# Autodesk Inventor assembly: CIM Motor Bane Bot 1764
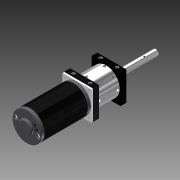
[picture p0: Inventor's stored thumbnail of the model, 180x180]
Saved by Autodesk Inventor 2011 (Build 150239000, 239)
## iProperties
Created: 2008-01
Part Number: CIM Motor Bane Bot 1764
Document SubType Name: Assembly
Designer: clee1
Author: clee1
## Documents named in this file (8)
- R:\CAD Archives\Motors\CIM Motor Bane Bots 1764\CIM Motor Bane Bot 1764.iam
- R:\CAD Archives\Motors\CIM Motor Bane Bots 1764\BB2-InterfacePlate 1764.ipt
- R:\CAD Archives\Motors\CIM Motor Bane Bots 1764\BB2-BackPlate 1764.ipt
- R:\CAD Archives\Motors\CIM Motor Bane Bots 1764\BB2-FrontPlate 1764.ipt
- R:\CAD Archives\Motors\CIM Motor Bane Bots 1764\CIM Bearing 1764.ipt
- R:\CAD Archives\Motors\CIM Motor Bane Bots 1764\BB2-RingGear 1764.ipt
- R:\CAD Archives\Motors\CIM Motor Bane Bots 1764\BB2-OutputShaft 2008 Cut 1764.ipt
- R:\CAD Archives\Motors\CIM Motor Bane Bots 1764\CIM Motor 1764.ipt
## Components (8 placed, 7 different names)
1. BB2-InterfacePlate 1764:1 — Mate:1, Flush:1, Flush:2, Mate:12
2. BB2-BackPlate 1764:1 — Mate:1, Flush:1, Flush:2, Mate:5, Mate:6, Angle:1, Angle:2, Mate:11, Angle:4, Flush:3, Flush:4
3. BB2-FrontPlate 1764:1 — Angle:2, Tangent:1, Tangent:2, Mate:13, Flush:3, Flush:4, Flush:5
4. CIM Bearing 1764:3 — Mate:3, Tangent:2
5. CIM Bearing 1764:4 — Mate:3, Tangent:1, Tangent:3, Flush:5, Mate:14
6. BB2-RingGear 1764:1 — Mate:5, Mate:6, Angle:1, Mate:13
7. BB2-OutputShaft 2008 Cut 1764:1 — Tangent:3, Mate:14, Mate:15
8. CIM Motor 1764:1 — Mate:11, Angle:4, Mate:12, Mate:15
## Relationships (20: Mate 9, Flush 5, Angle 3, Tangent 3)
- Mate:1: BB2-InterfacePlate 1764:1 ↔ BB2-BackPlate 1764:1
- Flush:1: BB2-InterfacePlate 1764:1 ↔ BB2-BackPlate 1764:1
- Flush:2: BB2-InterfacePlate 1764:1 ↔ BB2-BackPlate 1764:1
- Mate:3: CIM Bearing 1764:3 ↔ CIM Bearing 1764:4
- Mate:5: BB2-BackPlate 1764:1 ↔ BB2-RingGear 1764:1
- Mate:6: BB2-BackPlate 1764:1 ↔ BB2-RingGear 1764:1
- Angle:1: BB2-BackPlate 1764:1 ↔ BB2-RingGear 1764:1
- Angle:2: BB2-BackPlate 1764:1 ↔ BB2-FrontPlate 1764:1
- Mate:11: BB2-BackPlate 1764:1 ↔ CIM Motor 1764:1
- Angle:4: BB2-BackPlate 1764:1 ↔ CIM Motor 1764:1
- Mate:12: BB2-InterfacePlate 1764:1 ↔ CIM Motor 1764:1
- Tangent:1: BB2-FrontPlate 1764:1 ↔ CIM Bearing 1764:4
- Tangent:2: BB2-FrontPlate 1764:1 ↔ CIM Bearing 1764:3
- Mate:13: BB2-FrontPlate 1764:1 ↔ BB2-RingGear 1764:1
- Flush:3: BB2-BackPlate 1764:1 ↔ BB2-FrontPlate 1764:1
- Tangent:3: CIM Bearing 1764:4 ↔ BB2-OutputShaft 2008 Cut 1764:1
- Flush:4: BB2-BackPlate 1764:1 ↔ BB2-FrontPlate 1764:1
- Flush:5: BB2-FrontPlate 1764:1 ↔ CIM Bearing 1764:4
- Mate:14: CIM Bearing 1764:4 ↔ BB2-OutputShaft 2008 Cut 1764:1
- Mate:15: BB2-OutputShaft 2008 Cut 1764:1 ↔ CIM Motor 1764:1
